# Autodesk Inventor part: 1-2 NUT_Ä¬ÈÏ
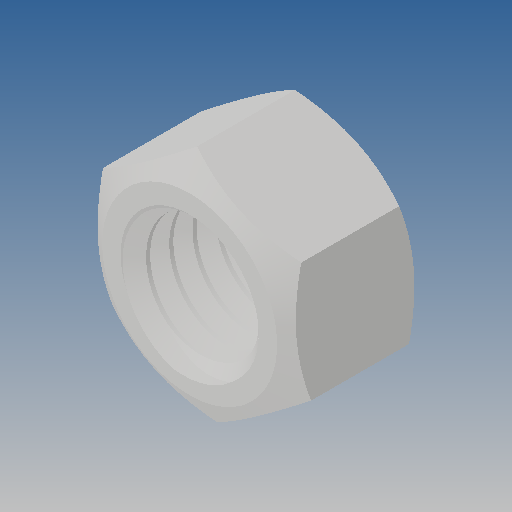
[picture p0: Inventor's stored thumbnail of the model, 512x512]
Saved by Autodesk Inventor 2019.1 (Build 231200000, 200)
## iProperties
Created: 2010-06
Part Number: 1-2 NUT_Ä¬ÈÏ
Material: Ogólny
Document SubType Name: Modeling
Designer: CADENGINEERING4
Density: 1 g/cm^3
Appearance: Domyślna
Author: CADENGINEERING4
Revision Number: ÈÎºÎ
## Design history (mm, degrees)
feature "NONE"
node "Bryła1"
